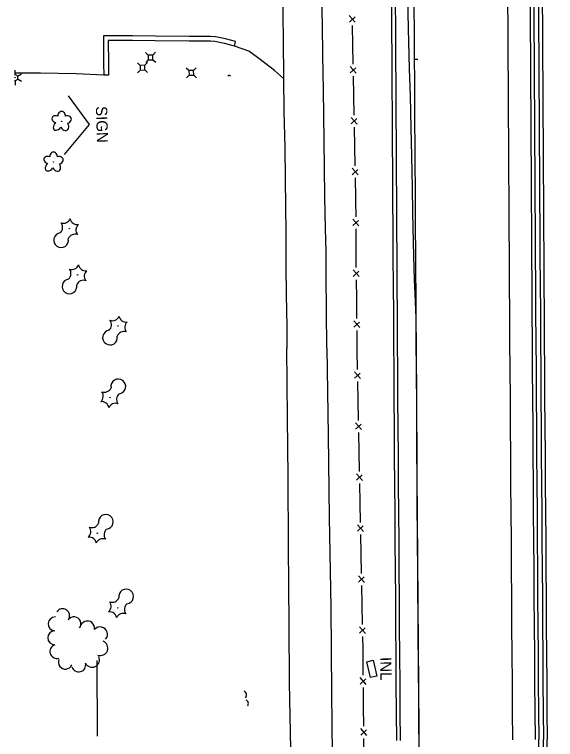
# Model space of a CAD drawing. Extents: x 588843 to 2552415, y 180129 to 269402.
# Drawn here: x 593742.5 to 594031.4, y 182730.2 to 183117.6 of the extents above; entities that cross this region are included whole.
import ezdxf

# ---------------------------------------------------------------- set-up
doc = ezdxf.new("R2010")
doc.units = 0
for name, color, linetype in [('Default', 7, 'Continuous'), ('E_DRN', 7, 'Continuous'), ('E_DRN_Text', 7, 'Continuous'), ('E_DWY', 7, 'Continuous'), ('E_FEN_P', 7, 'Continuous'), ('E_LAND_TreeLine_P', 7, 'Continuous'), ('E_LAND_Vegetation', 7, 'Continuous'), ('E_LTG', 7, 'Continuous'), ('E_RDWY', 7, 'Continuous'), ('E_RDWY_Gravel', 7, 'Continuous'), ('E_SGN', 7, 'Continuous'), ('E_SGN_Text', 7, 'Continuous'), ('E_UTL_AG_Bold', 7, 'Continuous'), ('E_WAL', 7, 'Continuous'), ('P_RDWY_BarrierConc', 7, 'Continuous'), ('P_RDWY_PavtEdge', 7, 'Continuous')]:
    doc.layers.add(name, color=color, linetype=linetype)

# ---------------------------------------------------------------- blocks, each defined once
blk = doc.blocks.new('CULV2')
at = {"layer": 'E_DRN'}
blk.add_arc((19.7, 14.8), 24.6, 216.8699, 323.1301, dxfattribs=at)
blk = doc.blocks.new('INLT_12')
at = {"layer": 'E_DRN_Text'}
blk.add_text('INL', height=12, dxfattribs=at).set_placement((-11.03, -6))
blk = doc.blocks.new('CTRE')
at = {"layer": 'Default'}
blk.add_circle((0, 0), 0.223, dxfattribs=at)
for centre, start, end in [((-11.97, 8.96), 280.2067, 5.97162), ((1.81, 14.92), 220.21132, 305.97623), ((13.83, 5.89), 160.21133, 245.97624), ((-13.83, -5.9), 340.21132, 65.97623), ((-1.81, -14.93), 40.21133, 125.97624), ((12.03, -9.04), 185.92721, 100.25111)]:
    blk.add_arc(centre, 7.87, start, end, dxfattribs=at)
blk = doc.blocks.new('PED')
at = {"layer": 'Default'}
for p, q in [((-2.5, 2.5), (-5.33, 5.33)), ((2.5, 2.5), (5.33, 5.33)), ((-2.5, -2.5), (-5.33, -5.33)), ((2.5, -2.5), (5.33, -5.33))]:
    blk.add_line(p, q, dxfattribs=at)
blk.add_lwpolyline([(-2.5, -2.5), (2.5, -2.5), (2.5, 2.5), (-2.5, 2.5)], close=True, dxfattribs=at)
blk = doc.blocks.new('SIGN')
at = {"layer": 'Default'}
blk.add_text('SIGN', height=12, dxfattribs=at).set_placement((-18.55, -6))
blk = doc.blocks.new('DTRE')
at = {"layer": 'Default'}
blk.add_circle((-0.18, 0), 0.183, dxfattribs=at)
for centre, major_axis, ratio in [((-1.87, 5.32), (1.36, -4.98), 0.782863), ((4.06, 2.74), (-5.27, -2.93), 0.691916), ((-5.87, 0.15), (4.93, -0.12), 0.832022), ((-2.49, -5.24), (1.8, 4.86), 0.716896), ((3.54, -3.71), (-5.01, 4.58), 0.560249)]:
    blk.add_ellipse(centre, major_axis=major_axis, ratio=ratio, start_param=1.570796, end_param=4.712389, dxfattribs=at)

msp = doc.modelspace()

# ---------------------------------------------------------------- linework, layer by layer
at = {"layer": 'E_DRN'}
msp.add_lwpolyline([(593932.58, 182763.26), (593930.59, 182771.74), (593934.06, 182772.54), (593936.05, 182764.06), (593932.58, 182763.26)], close=True, dxfattribs=at)
at = {"layer": 'E_DWY'}
for points in [[(593860.58, 183103.1), (593855.16, 183104.58), (593849.82, 183105.53), (593847.26, 183105.78), (593835.89, 183105.8), (593817.74, 183105.95), (593805.49, 183106.15), (593790.08, 183106.2), (593790.12, 183091.21), (593790.19, 183085.19)], [(593859.92, 183100.69), (593854.61, 183102.14), (593849.48, 183103.05), (593847.13, 183103.28), (593835.87, 183103.3), (593817.71, 183103.45), (593805.47, 183103.65), (593792.59, 183103.69), (593792.62, 183091.22), (593792.69, 183085.22)], [(593886.08, 183083.27), (593881.33, 183087.56), (593876.78, 183091.25), (593872.34, 183094.62), (593867.57, 183097.88), (593859.92, 183100.69), (593860.58, 183103.1)], [(593792.69, 183085.22), (593790.19, 183085.19), (593775.47, 183085.77), (593756.48, 183086.18), (593742.51, 183086.17)]]:
    msp.add_lwpolyline(points, dxfattribs=at)
at = {"layer": 'E_FEN_P'}
for p, q in [((593924.51, 183113.37), (593921.29, 183116.93)), ((593921.36, 183113.48), (593924.39, 183116.26)), ((593924.97, 183086.19), (593921.76, 183089.75)), ((593921.82, 183086.3), (593924.85, 183089.08)), ((593925.45, 183059.02), (593922.23, 183062.57)), ((593922.3, 183059.12), (593925.32, 183061.91)), ((593926.01, 183031.85), (593922.79, 183035.4)), ((593922.86, 183031.95), (593925.89, 183034.73)), ((593926.36, 183004.65), (593923.19, 183008.25)), ((593923.21, 183004.8), (593926.28, 183007.53)), ((593926.53, 182977.48), (593923.34, 182981.05)), ((593923.38, 182977.6), (593926.43, 182980.36)), ((593926.88, 182950.3), (593923.69, 182953.87)), ((593923.73, 182950.42), (593926.78, 182953.18)), ((593927.3, 182923.09), (593924.08, 182926.66)), ((593924.14, 182923.2), (593927.18, 182925.98)), ((593927.76, 182895.85), (593924.54, 182899.42)), ((593924.6, 182895.96), (593927.64, 182898.74)), ((593928.3, 182868.62), (593925.07, 182872.18)), ((593925.14, 182868.72), (593928.17, 182871.51)), ((593928.83, 182841.38), (593925.61, 182844.94)), ((593925.68, 182841.48), (593928.71, 182844.27)), ((593929.37, 182814.13), (593926.15, 182817.7)), ((593926.21, 182814.24), (593929.25, 182817.03)), ((593929.91, 182786.89), (593926.68, 182790.45)), ((593926.75, 182787), (593929.79, 182789.78)), ((593930.29, 182759.64), (593927.09, 182763.23)), ((593927.13, 182759.77), (593930.19, 182762.53)), ((593930.58, 182732.4), (593927.39, 182735.98)), ((593927.43, 182732.53), (593930.49, 182735.29))]:
    msp.add_line(p, q, dxfattribs=at)
for points in [[(593923.26, 183101.37), (593923.08, 183111.75)], [(593923.43, 183091), (593923.26, 183101.37)], [(593923.72, 183074.2), (593923.54, 183084.57)], [(593923.9, 183063.82), (593923.9, 183063.86), (593923.72, 183074.2)], [(593924.24, 183047.02), (593924.03, 183057.4)], [(593924.46, 183036.64), (593924.24, 183047.02)], [(593924.81, 183019.84), (593924.59, 183030.22)], [(593924.88, 183009.47), (593924.85, 183018), (593924.81, 183019.84)], [(593924.95, 182992.66), (593924.91, 183003.04)], [(593925.01, 182982.29), (593924.99, 182984.04), (593924.95, 182992.66)], [(593925.23, 182965.49), (593925.1, 182975.86)], [(593925.36, 182955.11), (593925.23, 182965.49)], [(593925.58, 182938.31), (593925.45, 182948.68)], [(593925.76, 182927.91), (593925.58, 182938.31)], [(593926.04, 182911.07), (593925.87, 182921.47)], [(593926.22, 182900.66), (593926.04, 182911.07)], [(593926.54, 182883.82), (593926.33, 182894.23)], [(593926.74, 182873.42), (593926.54, 182883.82)], [(593927.08, 182856.58), (593926.87, 182866.99)], [(593927.28, 182846.18), (593927.08, 182856.58)], [(593927.61, 182829.34), (593927.41, 182839.75)], [(593927.82, 182818.94), (593927.61, 182829.34)], [(593928.15, 182802.1), (593927.95, 182812.51)], [(593928.36, 182791.7), (593928.15, 182802.1)], [(593928.66, 182774.86), (593928.62, 182778.4), (593928.49, 182785.27)], [(593928.77, 182764.46), (593928.66, 182774.86)], [(593928.96, 182747.62), (593928.85, 182758.02)], [(593929.07, 182737.22), (593928.96, 182747.62)], [(593929.26, 182720.38), (593929.14, 182730.78)]]:
    msp.add_lwpolyline(points, dxfattribs=at)
at = {"layer": 'E_LAND_TreeLine_P'}
for centre, radius, start, end in [((593768.2, 182796.33), 3.73, 326.505, 146.505), ((593764.16, 182791.93), 3.73, 87.2161, 267.2161), ((593774.25, 182791.98), 3.73, 323.5374, 143.5374), ((593781.4, 182789.56), 3.93, 350.7637, 170.7637), ((593763.97, 182784.48), 3.73, 90.4872, 270.4872), ((593788.24, 182786.38), 3.93, 318.1463, 138.1463), ((593765.14, 182777.2), 3.73, 107.1339, 287.1339), ((593788.43, 182779), 3.93, 249.6092, 69.6092), ((593769.65, 182771.52), 3.73, 157.16, 337.16), ((593783.94, 182772.72), 3.93, 205.8529, 25.8529), ((593776.8, 182770.03), 3.73, 195.2411, 15.2411)]:
    msp.add_arc(centre, radius, start, end, dxfattribs=at)
at = {"layer": 'E_LTG'}
for p, q in [((593742.67, 183087.82), (593742.74, 183085.32)), ((593744.06, 183084.61), (593746.19, 183085.92)), ((593742.82, 183082.33), (593742.89, 183079.83)), ((593744.1, 183083.11), (593746.3, 183081.92))]:
    msp.add_line(p, q, dxfattribs=at)
msp.add_circle((593742.78, 183083.82), 0.125, dxfattribs=at)
msp.add_arc((593742.78, 183083.82), 1.5, 260.2665, 100.1322, dxfattribs=at)
at = {"layer": 'E_RDWY'}
for points in [[(593885.75, 183125.82), (593885.83, 183117.03), (593886.02, 183104.25), (593886.08, 183083.59), (593886.36, 183065.86), (593886.8, 183046.28), (593887, 183029.74), (593887.14, 183014.9), (593887.33, 183001.01), (593887.46, 182982.69), (593887.66, 182967.87), (593887.89, 182950.87), (593887.92, 182939.09)], [(593909.31, 182939.34), (593909.13, 182959.36), (593908.95, 182977.55), (593908.88, 182991.11), (593908.62, 183003.24), (593908.21, 183020.07), (593907.99, 183035.5), (593907.82, 183050.31), (593907.7, 183063.61), (593907.46, 183077.26), (593907.1, 183095.74), (593906.95, 183111.92), (593906.71, 183125.83)], [(593892.83, 182339.74), (593892.47, 182371.81), (593892.35, 182410.49), (593892.28, 182438.95), (593891.95, 182468.41), (593891.65, 182498.96), (593891.53, 182530.11), (593891.28, 182562.07), (593890.99, 182604.95), (593890.64, 182647.93), (593890.5, 182681.62), (593890.05, 182725.22), (593889.29, 182760.42), (593889.1, 182791.5), (593888.84, 182833.44), (593888.64, 182870.47), (593888.32, 182902.13), (593887.92, 182939.09)], [(593909.31, 182939.34), (593909.99, 182892.76), (593910.48, 182848.81), (593911.43, 182800.87), (593911.87, 182754.87), (593912.37, 182705.86), (593912.78, 182650.87), (593913.19, 182595.54), (593913.47, 182544.23), (593913.6, 182497.19), (593914.37, 182445.23), (593914.53, 182398.22), (593914.66, 182370.76), (593915.11, 182338.51)]]:
    msp.add_lwpolyline(points, dxfattribs=at)
at = {"layer": 'E_RDWY_Gravel'}
for points in [[(593952.39, 183127.13), (593952.79, 183110.13), (593953.32, 183088.56), (593953.72, 183074.11), (593954.1, 183057.08), (593954.48, 183041.8), (593954.81, 183025.03), (593955.13, 183011.45), (593955.55, 182988.49), (593955.95, 182975.9), (593956.35, 182968.4), (593956.9, 182955.23), (593957, 182940.14)], [(593961.64, 182331.65), (593961.27, 182366.32), (593961.01, 182415.15), (593960.66, 182458.51), (593960.31, 182500.45), (593960.09, 182534.66), (593959.79, 182572.79), (593959.48, 182607.03), (593959.14, 182643.74), (593958.92, 182677.5), (593958.62, 182714.32), (593958.48, 182751.45), (593958.07, 182787.03), (593957.85, 182818.62), (593957.54, 182856.48), (593957.32, 182897.87), (593957.27, 182920.34), (593957, 182940.14)]]:
    msp.add_lwpolyline(points, dxfattribs=at)
at = {"layer": 'E_SGN'}
for points in [[(593782.61, 183058.8), (593771.33, 183074.15)], [(593769.28, 183042.66), (593782.61, 183058.8)]]:
    msp.add_lwpolyline(points, dxfattribs=at)
at = {"layer": 'E_WAL'}
msp.add_lwpolyline([(593786.77, 182731.89), (593786.69, 182772.32)], dxfattribs=at)
at = {"layer": 'P_RDWY_BarrierConc'}
for p, q in [((594026.9, 182169), (594022.46, 182730.19)), ((594029.4, 182169.02), (594024.96, 182730.21)), ((594031.4, 182169.04), (594026.96, 182730.23))]:
    msp.add_line(p, q, dxfattribs=at)
for radius, start in [(171884.59, 180.1287302), (171882.59, 180.1287302), (171880.09, 180.1287302), (171878.09, 180.1287302), (171958.59, 180.290989), (171956.59, 180.290989)]:
    msp.add_arc((765899.68, 184089.33), radius, start, 180.4530652, dxfattribs=at)
at = {"layer": 'P_RDWY_PavtEdge'}
msp.add_line((593955.97, 183093.61), (593957.97, 183093.62), dxfattribs=at)
for radius, start, end in [(171896.59, 180.1287302, 180.4530652), (171946.59, 180.3112583, 180.3317952), (171946.59, 180.3317952, 180.4530652)]:
    msp.add_arc((765899.68, 184089.33), radius, start, end, dxfattribs=at)

# ---------------------------------------------------------------- block references
at = {"layer": 'E_DRN'}
for p, xscale, yscale, rotation in [((593857.87, 183084.63), 0.035372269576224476, 0.035372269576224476, 178.03677634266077), ((593865.88, 182752.48), 0.09341770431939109, 0.09341770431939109, 102.09932894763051), ((593866.98, 182748.23), 0.07658720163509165, 0.07658720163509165, 103.24509177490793)]:
    msp.add_blockref('CULV2', p, dxfattribs=dict(at, xscale=xscale, yscale=yscale, rotation=rotation))
at = {"layer": 'E_DRN_Text', "xscale": 0.49999999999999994, "yscale": 0.49999999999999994, "rotation": -89.28375254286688}
msp.add_blockref('INLT_12', (593940.85, 182768.7), dxfattribs=at)
at = {"layer": 'E_LAND_Vegetation'}
for name, p, xscale, yscale, rotation in [('DTRE', (593767.69, 183060.37), 0.5, 0.5, -88.44006292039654), ('DTRE', (593763.36, 183038.61), 0.5, 0.5, -88.44006292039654), ('CTRE', (593771.76, 183003.1), 0.5, 0.5, -88.44006292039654), ('CTRE', (593776.23, 182978.43), 0.5, 0.5, -88.44006292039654), ('CTRE', (593797.85, 182951.05), 0.5, 0.5, -88.44006292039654), ('CTRE', (593793.47, 182912.78), 0.5000000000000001, 0.5000000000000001, 90.45304071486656), ('CTRE', (593786.79, 182840.41), 0.5000000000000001, 0.5000000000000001, 90.45304071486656), ('CTRE', (593797.65, 182800.52), 0.5000000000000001, 0.5000000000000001, 90.45304071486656)]:
    msp.add_blockref(name, p, dxfattribs=dict(at, xscale=xscale, yscale=yscale, rotation=rotation))
at = {"layer": 'E_SGN_Text', "xscale": 0.5, "yscale": 0.5, "rotation": -88.44006292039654}
msp.add_blockref('SIGN', (593789.23, 183059.33), dxfattribs=at)
at = {"layer": 'E_UTL_AG_Bold', "xscale": 0.5, "yscale": 0.5, "rotation": -88.44006292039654}
for p in [(593815.18, 183094.62), (593810.86, 183089.15), (593836.92, 183086.36)]:
    msp.add_blockref('PED', p, dxfattribs=at)

doc.saveas('drawing.dxf')
